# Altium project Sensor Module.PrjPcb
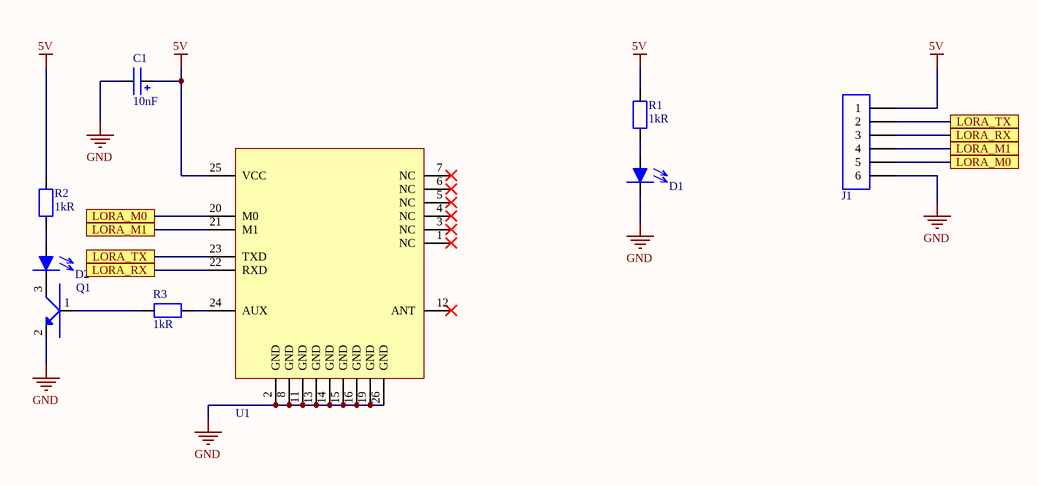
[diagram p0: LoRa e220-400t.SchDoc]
4 sheets, 70 parts. Net scope: flat (ports and power ports of the same name join across sheets).
Board file: Modules.PcbDoc
Sheets:
  LoRa e220-400t.SchDoc
  BNO055.SchDoc
  L76.SchDoc
  GOMSIS.SchDoc

## Sheet LoRa e220-400t.SchDoc
size A4; SheetNumber: 1; SheetTotal: 4

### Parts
C1  value 10nF  [CAP 0603]  (hidden comment: CAP 0603)
D1  LTW-C191TLA  [LED 0603]  (value not drawn)
D2  LTW-C191TLA  [LED 0603]  (value not drawn)
J1  5-146285-6  [HMATHT00C61]  (value not drawn)
Q1  BC817-40  [SOT23-3]  (value not drawn)
R1  value 1kR  [RESISTOR 0603]  (hidden comment: RES 0603)
R2  value 1kR  [RESISTOR 0603]  (hidden comment: RES 0603)
R3  value 1kR  [RESISTOR 0603]  (hidden comment: RES 0603)
U1  E220-400  [E220-400T22S]  (value not drawn)

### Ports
LORA_M0, LORA_M1, LORA_RX, LORA_TX

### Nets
5V: C1.1 J1.1 R1.2 R2.2 U1.25(VCC)
GND: C1.2 D1.1 J1.6 Q1.2(S) U1.2(GND) U1.8(GND) U1.11(GND) U1.13(GND) U1.14(GND) U1.15(GND) U1.16(GND) U1.19(GND) U1.26(GND)
NetD1_2: D1.2 R1.1
NetD2_1: D2.1 Q1.3(D)
NetD2_2: D2.2 R2.1
NetJ1_2: J1.2 U1.23(TXD) ; port LORA_TX
NetJ1_3: J1.3 U1.22(RXD) ; port LORA_RX
NetJ1_4: J1.4 U1.21(M1) ; port LORA_M1
NetJ1_5: J1.5 U1.20(M0) ; port LORA_M0
NetQ1_1: Q1.1(G) R3.1
NetR3_2: R3.2 U1.24(AUX)

Not connected (* = marked no-connect by the designer): U1 1(NC)* 3(NC)* 4(NC)* 5(NC)* 6(NC)* 7(NC)* 12(ANT)*

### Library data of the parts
C1 = CAP 0603: Multilayer Ceramic Capacitor; Capacitor Type: MLCC
D1 D2 = LED 0603: Chip LED
J1 = HMATHT00C61: Header for PCB
Q1 = BC817-40: Transistor BJT; Transistor Type: NPN; Voltage: 45V; Current: 500mA
R1-R3 = RES 0603: SMD Chip Resistor
U1 = E220-400: RF Transceiver; Frequency: 433MHz

## Sheet BNO055.SchDoc
size A4; SheetNumber: 2; SheetTotal: 4
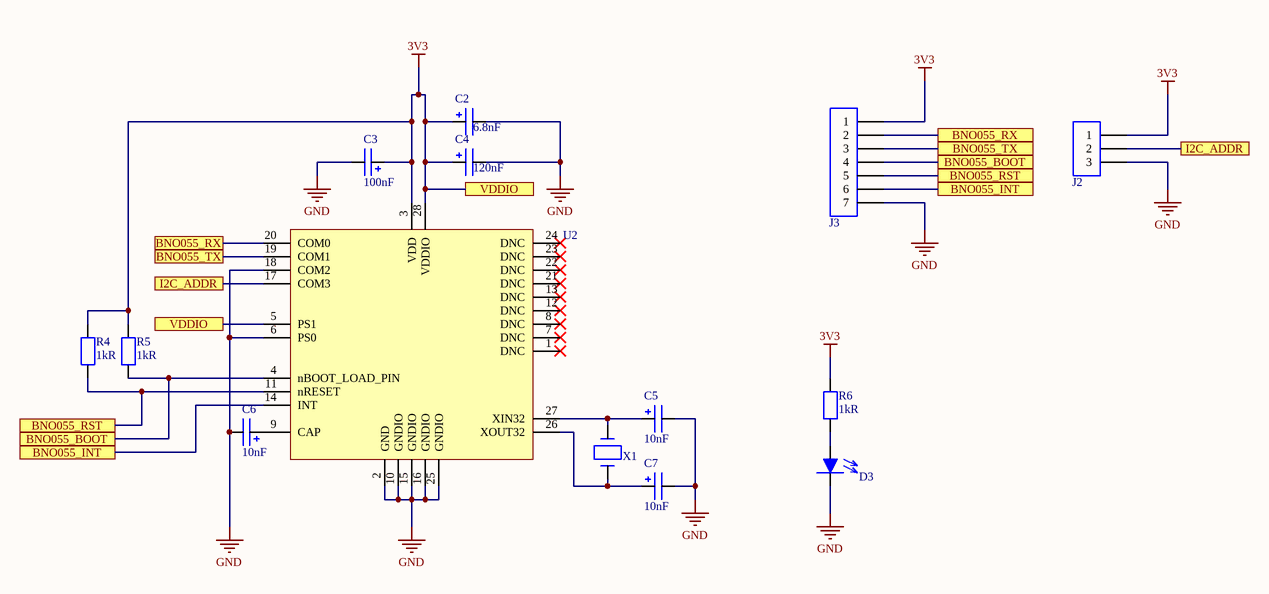
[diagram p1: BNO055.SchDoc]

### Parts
C2  value 6.8nF  [CAP 0603]  (hidden comment: CAP 0603)
C3  value 100nF  [CAP 0603]  (hidden comment: CAP 0603)
C4  value 120nF  [CAP 0603]  (hidden comment: CAP 0603)
C5  value 10nF  [CAP 0603]  (hidden comment: CAP 0603)
C6  value 10nF  [CAP 0603]  (hidden comment: CAP 0603)
C7  value 10nF  [CAP 0603]  (hidden comment: CAP 0603)
D3  LTW-C191TLA  [LED 0603]  (value not drawn)
J2  146285-3  [HMATHT00C31]  (value not drawn)
J3  825433-7  [HMATHT00C71]  (value not drawn)
R4  value 1kR  [RESISTOR 0603]  (hidden comment: RES 0603)
R5  value 1kR  [RESISTOR 0603]  (hidden comment: RES 0603)
R6  value 1kR  [RESISTOR 0603]  (hidden comment: RES 0603)
U2  BNO055  [LGA-28]  (value not drawn)
X1  RSM200S-32.768  [4-SOJ]  (value not drawn)

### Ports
BNO055_BOOT, BNO055_INT, BNO055_RST, BNO055_RX, BNO055_TX, I2C_ADDR, VDDIO

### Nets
3V3: C2.1 C3.1 C4.1 J2.1 J3.1 R4.2 R5.2 R6.2 U2.3(VDD) U2.5(PS1) U2.28(VDDIO) ; port VDDIO
GND: C2.2 C3.2 C4.2 C5.2 C6.2 C7.2 D3.1 J2.3 J3.7 U2.2(GND) U2.6(PS0) U2.10(GNDIO) U2.15(GNDIO) U2.16(GNDIO) U2.18(COM2) U2.25(GNDIO)
NetC5_1: C5.1 U2.27(XIN32) X1.4
NetC6_1: C6.1 U2.9(CAP)
NetC7_1: C7.1 U2.26(XOUT32) X1.1
NetD3_2: D3.2 R6.1
NetJ2_2: J2.2 U2.17(COM3) ; port I2C_ADDR
NetJ3_2: J3.2 U2.20(COM0) ; port BNO055_RX
NetJ3_3: J3.3 U2.19(COM1) ; port BNO055_TX
NetJ3_4: J3.4 R5.1 U2.4(nBOOT_LOAD_PIN) ; port BNO055_BOOT
NetJ3_5: J3.5 R4.1 U2.11(nRESET) ; port BNO055_RST
NetJ3_6: J3.6 U2.14(INT) ; port BNO055_INT

Not connected (* = marked no-connect by the designer): U2 1(DNC)* 7(DNC)* 8(DNC)* 12(DNC)* 13(DNC)* 21(DNC)* 22(DNC)* 23(DNC)* 24(DNC)*

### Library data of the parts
C2-C7 = CAP 0603: as C1 on sheet LoRa e220-400t
D3 = LED 0603: Chip LED
J2 = HMATHT00C31: Header for PCB
J3 = HMATHT00C71: Header for PCB
R4-R6 = RES 0603: SMD Chip Resistor
U2 = BNO055: IMU Sensor
X1 = RSM200S-32.768: CRYSTAL; Capacitance: 12.5pF

## Sheet L76.SchDoc
size A4; SheetNumber: 3; SheetTotal: 4
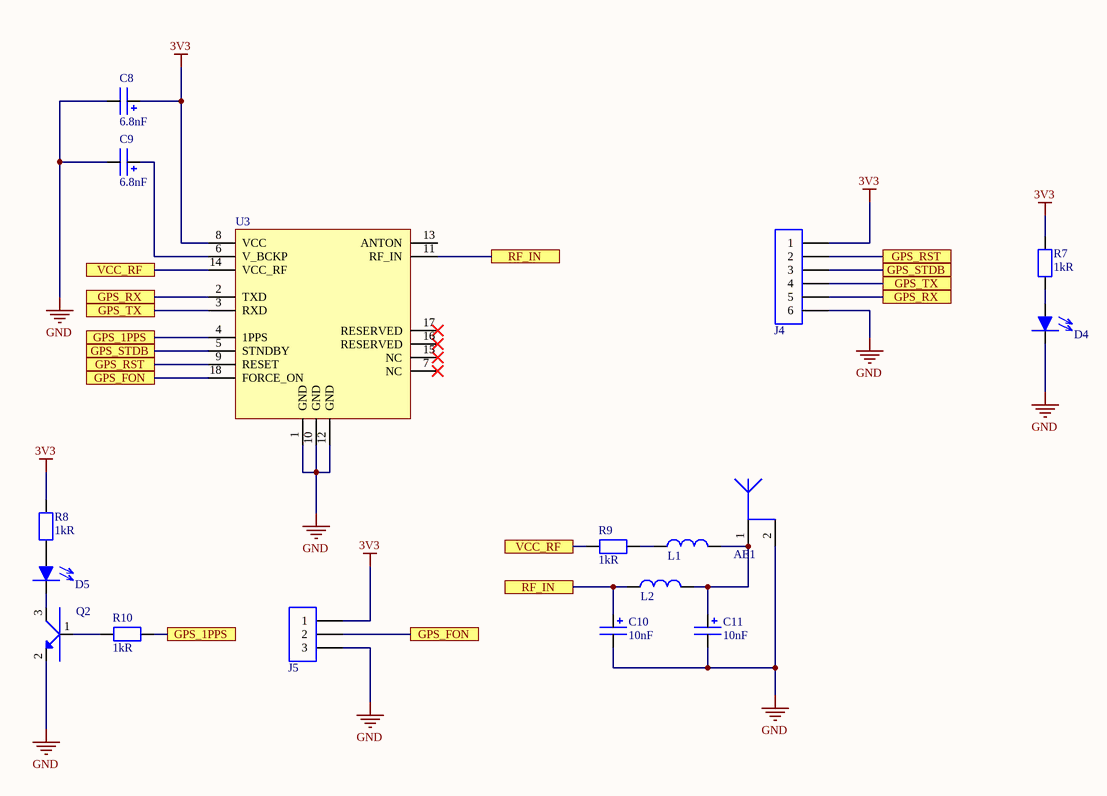
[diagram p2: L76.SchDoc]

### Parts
AE1  UFL Connector  [UFL CONN]  (value not drawn)
C8  value 6.8nF  [CAP 0603]  (hidden comment: CAP 0603)
C9  value 6.8nF  [CAP 0603]  (hidden comment: CAP 0603)
C10  value 10nF  [CAP 0603]  (hidden comment: CAP 0603)
C11  value 10nF  [CAP 0603]  (hidden comment: CAP 0603)
D4  LTW-C191TLA  [LED 0603]  (value not drawn)
D5  LTW-C191TLA  [LED 0603]  (value not drawn)
J4  5-146285-6  [HMATHT00C61]  (value not drawn)
J5  146285-3  [HMATHT00C31]  (value not drawn)
L1  IND 0603  [INDUCTOR 0603]  (value not drawn)
L2  IND 0603  [INDUCTOR 0603]  (value not drawn)
Q2  BC817-40  [SOT23-3]  (value not drawn)
R7  value 1kR  [RESISTOR 0603]  (hidden comment: RES 0603)
R8  value 1kR  [RESISTOR 0603]  (hidden comment: RES 0603)
R9  value 1kR  [RESISTOR 0603]  (hidden comment: RES 0603)
R10  value 1kR  [RESISTOR 0603]  (hidden comment: RES 0603)
U3  L76M33  [L76M33]  (value not drawn)

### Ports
GPS_1PPS, GPS_FON, GPS_RST, GPS_RX, GPS_STDB, GPS_TX, RF_IN, VCC_RF

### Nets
3V3: C8.1 J4.1 J5.1 R7.2 R8.2 U3.8(VCC)
GND: AE1.2 C8.2 C9.2 C10.2 C11.2 D4.1 J4.6 J5.3 Q2.2(S) U3.1(GND) U3.10(GND) U3.12(GND)
NetAE1_1: AE1.1 C11.1 L1.2 L2.2
NetC9_1: C9.1 U3.6(V_BCKP)
NetC10_1: C10.1 L2.1 U3.11(RF_IN) ; port RF_IN
NetD4_2: D4.2 R7.1
NetD5_1: D5.1 Q2.3(D)
NetD5_2: D5.2 R8.1
NetJ4_2: J4.2 U3.9(RESET) ; port GPS_RST
NetJ4_3: J4.3 U3.5(STNDBY) ; port GPS_STDB
NetJ4_4: J4.4 U3.3(RXD) ; port GPS_TX
NetJ4_5: J4.5 U3.2(TXD) ; port GPS_RX
NetJ5_2: J5.2 U3.18(FORCE_ON) ; port GPS_FON
NetL1_1: L1.1 R9.2
NetQ2_1: Q2.1(G) R10.1
NetR9_1: R9.1 U3.14(VCC_RF) ; port VCC_RF
NetR10_2: R10.2 U3.4(1PPS) ; port GPS_1PPS

Not connected (* = marked no-connect by the designer): U3 7(NC)* 13(ANTON) 15(NC)* 16(RESERVED)* 17(RESERVED)*

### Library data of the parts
AE1 = UFL Connector: Antenna Connector
C8-C11 = CAP 0603: as C1 on sheet LoRa e220-400t
D4 D5 = LED 0603: Chip LED
J4 = HMATHT00C61: Header for PCB
J5 = HMATHT00C31: Header for PCB
L1 L2 = IND 0603: SMD Inductor
Q2 = BC817-40: as Q1 on sheet LoRa e220-400t
R7-R10 = RES 0603: SMD Chip Resistor
U3 = L76M33: GPS, GLONASS, GNSS Transceiver

## Sheet GOMSIS.SchDoc
size A4; SheetNumber: 4; SheetTotal: 4
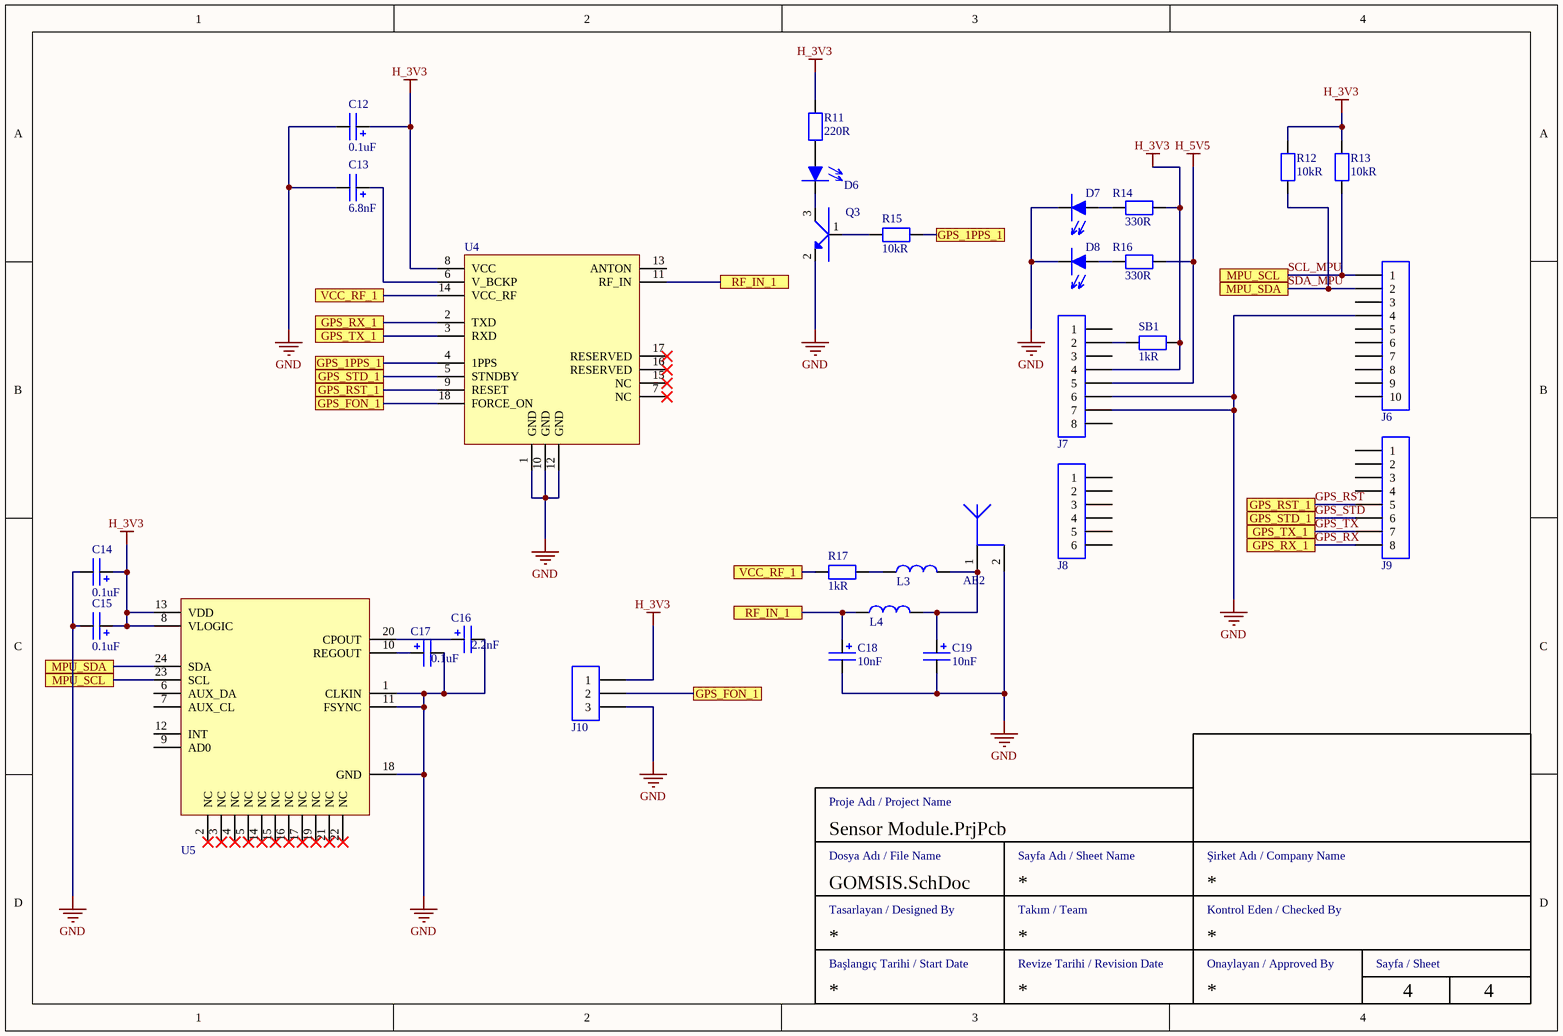
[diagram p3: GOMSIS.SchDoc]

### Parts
AE2  UFL Connector  [UFL CONN]  (value not drawn)
C12  value 0.1uF  [CAP 0603]  (hidden comment: CAP 0603)
C13  value 6.8nF  [CAP 0603]  (hidden comment: CAP 0603)
C14  value 0.1uF  [CAP 0603]  (hidden comment: CAP 0603)
C15  value 0.1uF  [CAP 0603]  (hidden comment: CAP 0603)
C16  value 2.2nF  [CAP 0603]  (hidden comment: CAP 0603)
C17  value 0.1uF  [CAP 0603]  (hidden comment: CAP 0603)
C18  value 10nF  [CAP 0603]  (hidden comment: CAP 0603)
C19  value 10nF  [CAP 0603]  (hidden comment: CAP 0603)
D6  LTW-C191TLA  [LED 0603]  (value not drawn)
D7  LTW-C191TLA  [LED 0603]  (value not drawn)
D8  LTW-C191TLA  [LED 0603]  (value not drawn)
J6  HMATHT00C101  [HMATHT00C101]  (value not drawn)
J7  HMATHT00C81  [HMATHT00C81 - duplicate]  (value not drawn)
J8  5-146285-6  [HMATHT00C61]  (value not drawn)
J9  HMATHT00C81  [HMATHT00C81 - duplicate]  (value not drawn)
J10  146285-3  [HMATHT00C31]  (value not drawn)
L3  IND 0603  [INDUCTOR 0603]  (value not drawn)
L4  IND 0603  [INDUCTOR 0603]  (value not drawn)
Q3  BC817-40  [SOT23-3]  (value not drawn)
R11  value 220R  [RESISTOR 0603]  (hidden comment: RES 0603)
R12  value 10kR  [RESISTOR 0603]  (hidden comment: RES 0603)
R13  value 10kR  [RESISTOR 0603]  (hidden comment: RES 0603)
R14  value 330R  [RESISTOR 0603]  (hidden comment: RES 0603)
R15  value 10kR  [RESISTOR 0603]  (hidden comment: RES 0603)
R16  value 330R  [RESISTOR 0603]  (hidden comment: RES 0603)
R17  value 1kR  [RESISTOR 0603]  (hidden comment: RES 0603)
SB1  value 1kR  [RESISTOR 0603]  (hidden comment: RES 0603)
U4  L76M33  [L76M33]  (value not drawn)
U5  MPU6050  [QFN24]  (value not drawn)

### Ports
GPS_1PPS_1, GPS_FON_1, GPS_RST_1, GPS_RX_1, GPS_STD_1, GPS_TX_1, MPU_SCL, MPU_SDA, RF_IN_1, VCC_RF_1

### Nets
GND: AE2.2 C12.2 C13.2 C14.2 C15.2 C16.2 C17.2 C18.2 C19.2 D7.1 D8.1 J6.4 J7.6 J7.7 J10.3 Q3.2(S) U4.1(GND) U4.10(GND) U4.12(GND) U5.1(CLKIN) U5.11(FSYNC) U5.18(GND)
H_3V3: C12.1 C14.1 C15.1 J7.4 J10.1 R11.2 R12.2 R13.2 R14.1 SB1.1 U4.8(VCC) U5.8(VLOGIC) U5.13(VDD)
H_5V5: J7.5 R16.1
GPS_RST: J9.5 U4.9(RESET) ; port GPS_RST_1
GPS_RX: J9.8 U4.2(TXD) ; port GPS_RX_1
GPS_STD: J9.6 U4.5(STNDBY) ; port GPS_STD_1
GPS_TX: J9.7 U4.3(RXD) ; port GPS_TX_1
SCL_MPU: J6.1 R13.1 U5.23(SCL) ; port MPU_SCL
SDA_MPU: J6.2 R12.1 U5.24(SDA) ; port MPU_SDA
NetAE2_1: AE2.1 C19.1 L3.2 L4.2
NetC13_1: C13.1 U4.6(V_BCKP)
NetC16_1: C16.1 U5.20(CPOUT)
NetC17_1: C17.1 U5.10(REGOUT)
NetC18_1: C18.1 L4.1 U4.11(RF_IN) ; port RF_IN_1
NetD6_1: D6.1 Q3.3(D)
NetD6_2: D6.2 R11.1
NetD7_2: D7.2 R14.2
NetD8_2: D8.2 R16.2
NetJ7_2: J7.2 SB1.2
NetJ10_2: J10.2 U4.18(FORCE_ON) ; port GPS_FON_1
NetL3_1: L3.1 R17.2
NetQ3_1: Q3.1(G) R15.1
NetR15_2: R15.2 U4.4(1PPS) ; port GPS_1PPS_1
NetR17_1: R17.1 U4.14(VCC_RF) ; port VCC_RF_1

Not connected (* = marked no-connect by the designer): J6 3 5 6 7 8 9 10; J7 1 3 8; J8 1 2 3 4 5 6; J9 1 2 3 4; U4 7(NC)* 13(ANTON) 15(NC)* 16(RESERVED)* 17(RESERVED)*; U5 2(NC)* 3(NC)* 4(NC)* 5(NC)* 6(AUX_DA) 7(AUX_CL) 9(AD0) 12(INT) 14(NC)* 15(NC)* 16(NC)* 17(NC)* 19(NC)* 21(NC)* 22(NC)*

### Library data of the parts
AE2 = UFL Connector: Antenna Connector
C12-C19 = CAP 0603: as C1 on sheet LoRa e220-400t
D6-D8 = LED 0603: Chip LED
J6 = HMATHT00C101: Header for PCB
J7 J9 = HMATHT00C81: Header for PCB
J8 = HMATHT00C61: Header for PCB
J10 = HMATHT00C31: Header for PCB
L3 L4 = IND 0603: SMD Inductor
Q3 = BC817-40: as Q1 on sheet LoRa e220-400t
R11-R17 SB1 = RES 0603: SMD Chip Resistor
U4 = L76M33: GPS, GLONASS, GNSS Transceiver
U5 = MPU6050: IMU

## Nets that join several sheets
3V3: BNO055 (11 pins), L76 (6 pins)
GND: LoRa e220-400t (13 pins), BNO055 (16 pins), L76 (12 pins), GOMSIS (22 pins)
